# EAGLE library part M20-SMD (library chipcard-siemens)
Siemens M20 CHIP CARD HOLDER
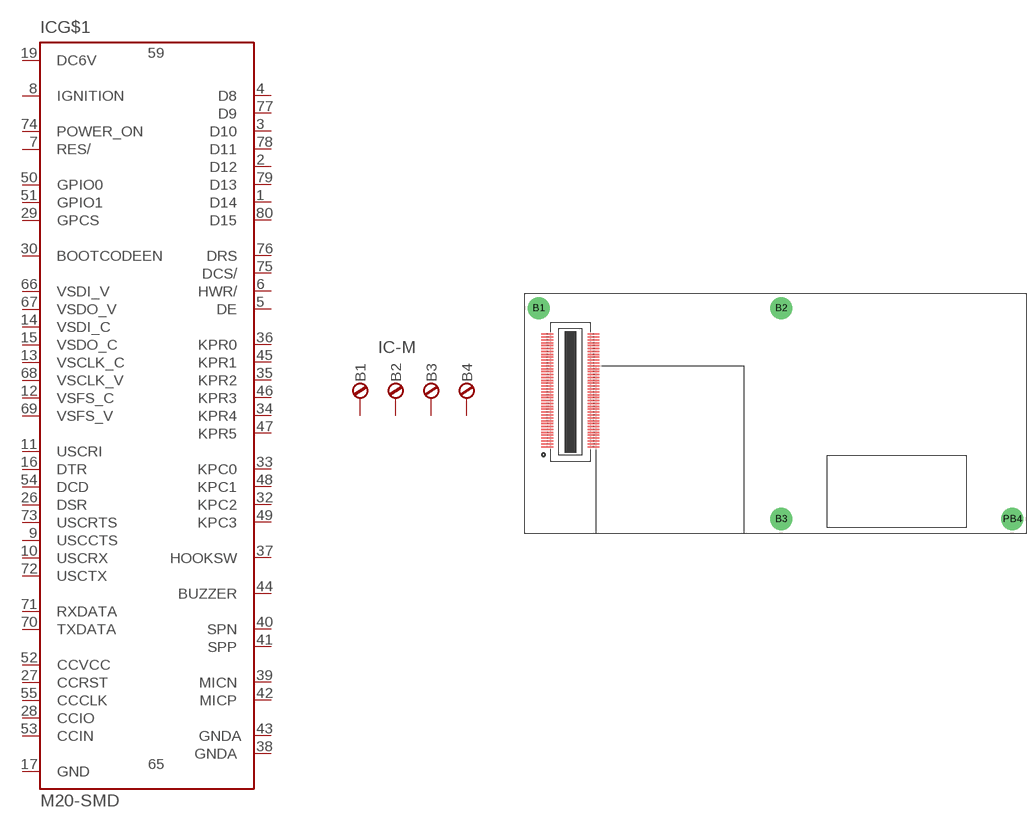
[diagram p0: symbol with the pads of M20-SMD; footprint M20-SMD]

Designator prefix IC; gates -M=M20-DRIL G$1=M20-SMD

## M20-SMD (OC_FARNELL: unknown; OC_NEWARK: unknown)  [M20-SMD]
1  G$1:D14
2  G$1:D12
3  G$1:D10
4  G$1:D8
5  G$1:DE  out
6  G$1:HWR/  out
7  G$1:RES/  out
8  G$1:IGNITION  in
9  G$1:USCCTS  in
10  G$1:USCRX  in
11  G$1:USCRI  out
12  G$1:VSFS_C  in
13  G$1:VSCLK_C  in
14  G$1:VSDI_C  in
15  G$1:VSDO_C  out
16  G$1:DTR  in
17  G$1:GND  pwr
18  G$1:DC6V  pwr
19  G$1:DC6V  pwr
20  G$1:DC6V  pwr
21  G$1:DC6V  pwr
22  G$1:DC6V  pwr
23  G$1:GND  pwr
24  G$1:GND  pwr
25  G$1:GND  pwr
26  G$1:DSR  out
27  G$1:CCRST  out
28  G$1:CCIO
29  G$1:GPCS  out
30  G$1:BOOTCODEEN  in
31  G$1:NC  nc
32  G$1:KPC2  out
33  G$1:KPC0  out
34  G$1:KPR4  in
35  G$1:KPR2  in
36  G$1:KPR0  in
37  G$1:HOOKSW  in
38  G$1:GNDA  pwr
39  G$1:MICN  in
40  G$1:SPN  out
41  G$1:SPP  out
42  G$1:MICP  in
43  G$1:GNDA  pwr
44  G$1:BUZZER  out
45  G$1:KPR1  in
46  G$1:KPR3  in
47  G$1:KPR5  in
48  G$1:KPC1  out
49  G$1:KPC3  out
50  G$1:GPIO0  in
51  G$1:GPIO1  in
52  G$1:CCVCC  out
53  G$1:CCIN  in
54  G$1:DCD  out
55  G$1:CCCLK  out
56  G$1:GND  pwr
57  G$1:GND  pwr
58  G$1:DC6V  pwr
59  G$1:DC6V  pwr
60  G$1:DC6V  pwr
61  G$1:DC6V  pwr
62  G$1:DC6V  pwr
63  G$1:GND  pwr
64  G$1:GND  pwr
65  G$1:GND  pwr
66  G$1:VSDI_V  in
67  G$1:VSDO_V  out
68  G$1:VSCLK_V  out
69  G$1:VSFS_V  out
70  G$1:TXDATA  out
71  G$1:RXDATA  in
72  G$1:USCTX  out
73  G$1:USCRTS  out
74  G$1:POWER_ON  out
75  G$1:DCS/  out
76  G$1:DRS  out
77  G$1:D9
78  G$1:D11
79  G$1:D13
80  G$1:D15
B1  -M:B1  pas
B2  -M:B2  pas
B3  -M:B3  pas
PB4  -M:B4  pas

## Footprint M20-SMD (pad centres in mm)
Siemens M20 CHIP CARD HOLDER
smd 2.007 x 0.254: 1 -4,-9.5; 2 -4,-9; 3 -4,-8.5; 4 -4,-8; 5 -4,-7.5; 6 -4,-7; 7 -4,-6.5; 8 -4,-6; 9 -4,-5.5; 10 -4,-5; 11 -4,-4.5; 12 -4,-4; 13 -4,-3.5; 14 -4,-3; 15 -4,-2.5; 16 -4,-2; 17 -4,-1.5; 18 -4,-1; 19 -4,-0.5; 20 -4,0; 21 -4,0.5; 22 -4,1; 23 -4,1.5; 24 -4,2; 25 -4,2.5; 26 -4,3; 27 -4,3.5; 28 -4,4; 29 -4,4.5; 30 -4,5; 31 -4,5.5; 32 -4,6; 33 -4,6.5; 34 -4,7; 35 -4,7.5; 36 -4,8; 37 -4,8.5; 38 -4,9; 39 -4,9.5; 40 -4,10; 41 4,10; 42 4,9.5; 43 4,9; 44 4,8.5; 45 4,8; 46 4,7.5; 47 4,7; 48 4,6.5; 49 4,6; 50 4,5.5; 51 4,5; 52 4,4.5; 53 4,4; 54 4,3.5; 55 4,3; 56 4,2.5; 57 4,2; 58 4,1.5; 59 4,1; 60 4,0.5; 61 4,0; 62 4,-0.5; 63 4,-1; 64 4,-1.5; 65 4,-2; 66 4,-2.5; 67 4,-3; 68 4,-3.5; 69 4,-4; 70 4,-4.5; 71 4,-5; 72 4,-5.5; 73 4,-6; 74 4,-6.5; 75 4,-7; 76 4,-7.5; 77 4,-8; 78 4,-8.5; 79 4,-9; 80 4,-9.5
drill 2.184 pad 3.81 round: B1 -5.5,14.5; B2 36.5,14.5; B3 36.5,-22; PB4 76.5,-22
